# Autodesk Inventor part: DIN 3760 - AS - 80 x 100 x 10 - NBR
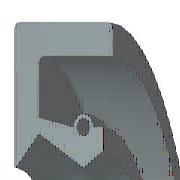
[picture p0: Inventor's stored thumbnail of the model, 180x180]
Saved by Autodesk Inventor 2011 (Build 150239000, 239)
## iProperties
IsCustomPart: 0
Created: 2010-02
Part Number: DIN 3760 - AS - 80 x 100 x 10 - NBR
Material: Rubber
Description: Shaft Seal Ring
Document SubType Name: Modeling
Standard: DIN 3760
Designer: 129877
Standards Organization: DIN
Language: en-US
Size Designation: AS - 80 x 100 x 10 - NBR
Categories: <MemberInstance><Categories><Category DisplayName="Shaft Parts" InternalName="7f7aeb1f-a693-4053-b835-cee3144e0d98" Mnemonic="SHFT"><Category DisplayName="Seali
Density: 0.93 g/cm^3
Mass: 15.005 g
Surface Area: 152.8 cm^2
Volume: 16.1344 cm^3
Author: 129877
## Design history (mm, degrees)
revolve "Body" stored, may be unused: angle "d17" = 90 deg
revolve "Spring1" stored, may be unused: angle "d18" = 90 deg
body "Solid1"
sketch "Sketch1"
  geometry: L1 (0, 50)-(10, 50); L2 (10, 47.5)-(2.5, 47.5); L3 (2.5, 42.5)-(7, 40); L4 (7, 40)-(0, 40); L5 (0, 0)-(9.586, 0) reference; L6 (7, 40)-(9, 41.25); L7 (0, 18)-(0, -3) reference; L8 (-1.941, 0)-(11.507, 0) reference; L9 (6, 43)-(2.5, 43.7); L10 (2.5, 43.7)-(2.5, 47.5); L11 (0, 50)-(0, 40.125); L12 (7, 40)-(0, 40); L13 (2.5, 42.5)-(0.217, 40.04); L14 (10, 50)-(10, 47.5); L15 (8, 43)-(9, 43); L16 (9, 43)-(9, 41.25); C1 r 0.65 at (7, 43); A1 r 1 centre (7, 43) between (8, 43) and (6, 43); A2 r 0.125 centre (0.125, 40.125) between (0, 40.125) and (0.217, 40.04); 1 further point
  constraints: 28 end point, 5 horizontal alignment, 5 point on line, 4 point on circle, 4 vertical alignment, 3 centre point, 3 tangent, 2 collinear, 2 horizontal, 2 perpendicular, 1 coincident, 1 parallel
  dimensions: "d0" = 100 diameter of L1 L5 (= SD2); "d1" = 2.5 distance of L1.end L2.start (= SD); "d2" = 1.3 diameter of C1 (= SPDI); "d3" = 2 diameter of A1 (= SPDA); "d4" = 80 diameter of L3.end L5 (= NND); "d5" = 85 diameter of L3.start L5 (= TKDM); "d7" = 87.4 diameter of L9.end L5 (= TKDM + 0.24 x SWDT); "d8" = 2.5 distance between parallel lines of L11 L10 (= SD); "d9" = 7 distance from line of L11 C1.centre (= SPDST); "d10" = 86 diameter of C1.centre L5 (= HLDM); "d11" = 0.125 radius of A2 (= 0.25 x LAB); "d12" = 9 distance between parallel lines of L11 L16 (= SDI); "d13" = 82.5 diameter of L6.end L5 (= ABDM); "d14" = 10 distance from line of L11 L1.end (= SWDT)
fillet "Fillet1" dims "d6" = 0.5 (= RR)
other parameters: "SD2" = 100 [user parameter; used in 1 equation term], "SWDT" = 10 [user parameter; used in 2 equation terms], "RR" = 0.5 [user parameter; used in 1 equation term], "SD" = 2.5 [user parameter; used in 2 equation terms], "NND" = 80 [user parameter; used in 1 equation term], "SPDA" = 2 [user parameter; used in 1 equation term], "SPDI" = 1.3 [user parameter; used in 1 equation term], "TKDM" = 85 [user parameter; used in 2 equation terms], "HLDM" = 86 [user parameter; used in 1 equation term], "ABDM" = 82.5 [user parameter; used in 1 equation term], "SDI" = 9 [user parameter; used in 1 equation term], "SPDST" = 7 [user parameter; used in 1 equation term], "LAB" = 0.5 [user parameter; used in 1 equation term], "d15" = 0, "d16" = 0, "d19" = 0
